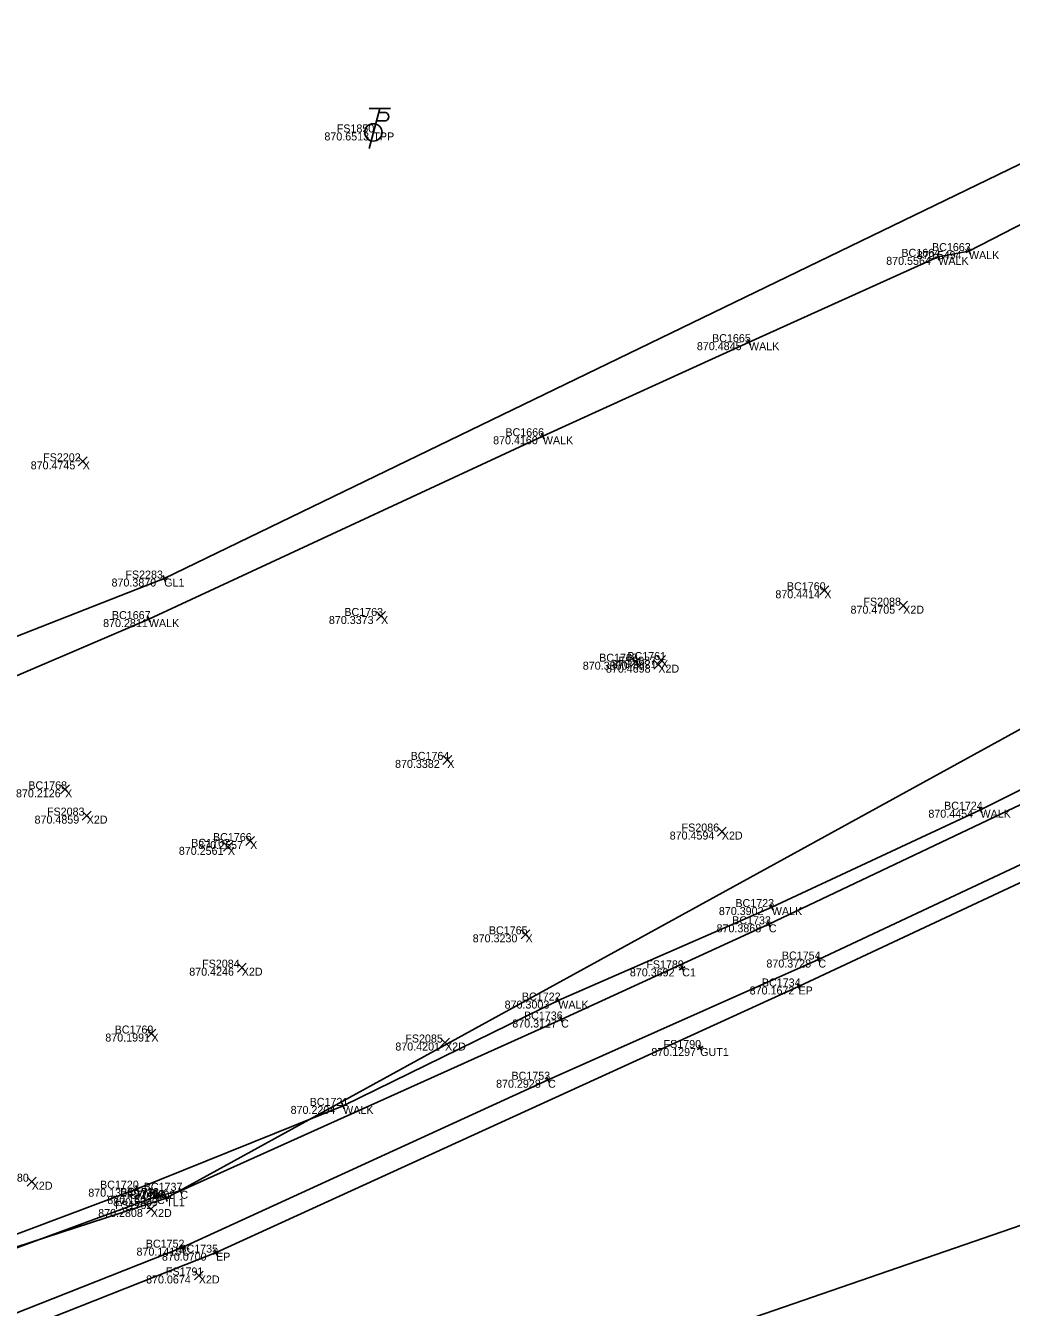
# Model space of a CAD drawing. Extents: x 1479425 to 1480294, y 379351 to 380102.
# Drawn here: x 1479669.9 to 1479677.28, y 379943.62 to 379953.22 of the extents above; entities that cross this region are included whole.
import ezdxf

# ---------------------------------------------------------------- set-up
doc = ezdxf.new("R2010")
doc.units = 0
for name, color, linetype in [('PV_X_Curb', 7, 'Continuous'), ('PV_X_Walk', 7, 'Continuous'), ('SV_X_Random_Point', 7, 'Continuous'), ('SV_X_Shot_Marker', 7, 'Continuous'), ('SV_X_Text_Comment', 7, 'Continuous'), ('SV_X_Text_Elevation', 7, 'Continuous'), ('SV_X_Text_Name', 7, 'Continuous'), ('UT_X_Gas', 7, 'Continuous'), ('UT_X_Misc_Cells', 7, 'Continuous'), ('UT_X_Sanitary_Line', 7, 'Continuous'), ('UT_X_Telecom', 7, 'Continuous')]:
    doc.layers.add(name, color=color, linetype=linetype)

msp = doc.modelspace()

# ---------------------------------------------------------------- linework, layer by layer
at = {"layer": 'PV_X_Curb'}
for points in [[(1479791.59, 380003.4635), (1479772.982, 379994.3805), (1479762.438, 379989.2296), (1479737.891, 379977.2252), (1479720.638, 379968.6113), (1479698.71, 379957.883), (1479682.4127, 379949.7895), (1479678.7563, 379947.9876), (1479678.5248, 379947.9422), (1479675.4654, 379946.4876), (1479673.9091, 379945.7738), (1479671.0561, 379944.4897), (1479670.8808, 379944.4504), (1479668.8369, 379943.6961), (1479667.0164, 379943.0245), (1479664.845, 379942.3912), (1479664.6467, 379942.3345), (1479664.117, 379942.1619), (1479661.876, 379941.9004), (1479659.999, 379941.9714), (1479653.935, 379943.2676), (1479649.182, 379945.5268), (1479644.261, 379948.8889)], [(1479791.848, 380002.9887), (1479773.254, 379993.8725), (1479762.766, 379988.7719), (1479738.122, 379976.6433), (1479720.845, 379968.2141), (1479698.694, 379957.2389), (1479682.744, 379949.3616), (1479678.8019, 379947.4796), (1479675.6873, 379946.0213), (1479671.3231, 379944.0259), (1479668.9901, 379943.1057), (1479665.6381, 379942.0412), (1479664.1435, 379941.5823), (1479662.026, 379941.3965), (1479659.994, 379941.5118), (1479654.023, 379942.7671), (1479648.758, 379945.1011), (1479643.81, 379948.5526)], [(1479664.2039, 379941.7379), (1479664.7376, 379941.8534), (1479664.9193, 379941.9176), (1479667.0854, 379942.5936), (1479669.0389, 379943.2625), (1479671.0702, 379944.0635), (1479673.8108, 379945.3222), (1479675.8363, 379946.2235), (1479678.7099, 379947.5729), (1479678.8669, 379947.6085), (1479682.6232, 379949.494)]]:
    msp.add_lwpolyline(points, dxfattribs=at)
at = {"layer": 'PV_X_Walk'}
for points in [[(1479680.531, 379953.5783), (1479680.5594, 379953.3846), (1479676.9646, 379951.5344), (1479676.7347, 379951.4915), (1479675.3165, 379950.8518), (1479673.7719, 379950.1464), (1479670.8196, 379948.7758), (1479669.4595, 379948.1937), (1479669.388, 379947.9546), (1479669.0403, 379947.6975), (1479668.7338, 379947.7557), (1479668.5535, 379947.8945), (1479667.7241, 379947.5602), (1479667.7995, 379947.6709), (1479667.4767, 379949.4768), (1479667.1248, 379951.2892), (1479667.1368, 379951.4103), (1479666.7498, 379953.3122), (1479666.5215, 379955.0904), (1479666.4393, 379955.1162), (1479666.0253, 379957.6131), (1479665.7712, 379958.9526), (1479665.7102, 379959.0342), (1479665.0761, 379962.8267)], [(1479668.8228, 379943.7878), (1479670.7322, 379944.5055), (1479672.2751, 379945.1262), (1479673.8874, 379945.9158), (1479675.4876, 379946.6168), (1479677.0508, 379947.3467), (1479678.4574, 379948.0505), (1479678.6848, 379948.0907), (1479682.4053, 379949.8566)]]:
    msp.add_lwpolyline(points, dxfattribs=at)
at = {"layer": 'SV_X_Random_Point'}
for p, q in [((1479670.2907, 379949.9251), (1479670.3573, 379949.9919)), ((1479670.2907, 379949.9919), (1479670.3573, 379949.9251)), ((1479675.8474, 379948.9584), (1479675.914, 379949.0252)), ((1479675.8474, 379949.0252), (1479675.914, 379948.9584)), ((1479676.4387, 379948.843), (1479676.5053, 379948.9098)), ((1479676.4387, 379948.9098), (1479676.5053, 379948.843)), ((1479672.5262, 379948.7656), (1479672.5928, 379948.8324)), ((1479672.5262, 379948.8324), (1479672.5928, 379948.7656)), ((1479674.4347, 379948.423), (1479674.5013, 379948.4898)), ((1479674.4347, 379948.4898), (1479674.5013, 379948.423)), ((1479674.6037, 379948.4009), (1479674.6703, 379948.4677)), ((1479674.6037, 379948.4677), (1479674.6703, 379948.4009)), ((1479674.6243, 379948.4351), (1479674.6909, 379948.5019)), ((1479674.6243, 379948.5019), (1479674.6909, 379948.4351)), ((1479673.0223, 379947.6867), (1479673.0889, 379947.7535)), ((1479673.0223, 379947.7535), (1479673.0889, 379947.6867)), ((1479670.1589, 379947.466), (1479670.2255, 379947.5328)), ((1479670.1589, 379947.5328), (1479670.2255, 379947.466)), ((1479670.3207, 379947.2691), (1479670.3873, 379947.3359)), ((1479670.3207, 379947.3359), (1479670.3873, 379947.2691)), ((1479675.0797, 379947.1495), (1479675.1463, 379947.2163)), ((1479675.0797, 379947.2163), (1479675.1463, 379947.1495)), ((1479671.3782, 379947.0349), (1479671.4448, 379947.1017)), ((1479671.3782, 379947.1017), (1479671.4448, 379947.0349)), ((1479671.5456, 379947.0781), (1479671.6122, 379947.1449)), ((1479671.5456, 379947.1449), (1479671.6122, 379947.0781)), ((1479673.6089, 379946.3791), (1479673.6755, 379946.4459)), ((1479673.6089, 379946.4459), (1479673.6755, 379946.3791)), ((1479671.4827, 379946.129), (1479671.5493, 379946.1958)), ((1479671.4827, 379946.1958), (1479671.5493, 379946.129)), ((1479670.8056, 379945.6351), (1479670.8722, 379945.7019)), ((1479670.8056, 379945.7019), (1479670.8722, 379945.6351)), ((1479673.0057, 379945.5679), (1479673.0723, 379945.6347)), ((1479673.0057, 379945.6347), (1479673.0723, 379945.5679)), ((1479669.9087, 379944.5244), (1479669.9753, 379944.5912)), ((1479669.9087, 379944.5912), (1479669.9753, 379944.5244)), ((1479670.8017, 379944.3197), (1479670.8683, 379944.3865)), ((1479670.8017, 379944.3865), (1479670.8683, 379944.3197)), ((1479671.1607, 379943.8214), (1479671.2273, 379943.8882)), ((1479671.1607, 379943.8882), (1479671.2273, 379943.8214))]:
    msp.add_line(p, q, dxfattribs=at)
at = {"layer": 'SV_X_Shot_Marker'}
for p, q in [((1479676.7593, 379951.4961), (1479676.7101, 379951.4869)), ((1479676.7393, 379951.4669), (1479676.7301, 379951.5161)), ((1479676.7347, 379951.4915), (1479676.7347, 379951.4915)), ((1479676.9868, 379951.5459), (1479676.9424, 379951.523)), ((1479676.976, 379951.5122), (1479676.9532, 379951.5566)), ((1479676.9646, 379951.5344), (1479676.9646, 379951.5344)), ((1479675.3393, 379950.8621), (1479675.2937, 379950.8415)), ((1479675.3268, 379950.829), (1479675.3062, 379950.8746)), ((1479675.3165, 379950.8518), (1479675.3165, 379950.8518)), ((1479673.7946, 379950.1568), (1479673.7492, 379950.136)), ((1479673.7823, 379950.1237), (1479673.7615, 379950.1692)), ((1479673.7719, 379950.1464), (1479673.7719, 379950.1464)), ((1479670.9117, 379949.0705), (1479670.9583, 379949.0887)), ((1479670.9259, 379949.1029), (1479670.9441, 379949.0563)), ((1479670.935, 379949.0796), (1479670.935, 379949.0796)), ((1479670.8301, 379948.7531), (1479670.8091, 379948.7985)), ((1479670.8423, 379948.7863), (1479670.7969, 379948.7653)), ((1479670.8196, 379948.7758), (1479670.8196, 379948.7758)), ((1479677.0281, 379947.3361), (1479677.0734, 379947.3573)), ((1479677.0402, 379947.3694), (1479677.0614, 379947.3241)), ((1479677.0508, 379947.3467), (1479677.0508, 379947.3467)), ((1479675.4647, 379946.6068), (1479675.5105, 379946.6269)), ((1479675.4776, 379946.6397), (1479675.4976, 379946.5939)), ((1479675.4876, 379946.6168), (1479675.4876, 379946.6168)), ((1479675.488, 379946.4984), (1479675.4428, 379946.4769)), ((1479675.4761, 379946.465), (1479675.4547, 379946.5102)), ((1479675.4654, 379946.4876), (1479675.4654, 379946.4876)), ((1479675.8135, 379946.2134), (1479675.8591, 379946.2337)), ((1479675.8261, 379946.2464), (1479675.8465, 379946.2007)), ((1479675.8363, 379946.2235), (1479675.8363, 379946.2235)), ((1479674.8383, 379946.1685), (1479674.7937, 379946.1458)), ((1479674.8273, 379946.1348), (1479674.8047, 379946.1794)), ((1479674.816, 379946.1571), (1479674.816, 379946.1571)), ((1479675.7099, 379946.0319), (1479675.6647, 379946.0107)), ((1479675.6979, 379945.9987), (1479675.6767, 379946.044)), ((1479675.6873, 379946.0213), (1479675.6873, 379946.0213)), ((1479673.8649, 379945.9048), (1479673.9098, 379945.9268)), ((1479673.8764, 379945.9383), (1479673.8984, 379945.8934)), ((1479673.8874, 379945.9158), (1479673.8874, 379945.9158)), ((1479673.9318, 379945.7842), (1479673.8864, 379945.7634)), ((1479673.9195, 379945.7511), (1479673.8987, 379945.7965)), ((1479673.9091, 379945.7738), (1479673.9091, 379945.7738)), ((1479674.9732, 379945.5715), (1479674.9287, 379945.5487)), ((1479674.9624, 379945.5379), (1479674.9396, 379945.5824)), ((1479674.951, 379945.5601), (1479674.951, 379945.5601)), ((1479673.8004, 379945.3449), (1479673.8212, 379945.2995)), ((1479673.7881, 379945.3118), (1479673.8335, 379945.3327)), ((1479673.8108, 379945.3222), (1479673.8108, 379945.3222)), ((1479672.2658, 379945.1494), (1479672.2844, 379945.103)), ((1479672.2519, 379945.1169), (1479672.2983, 379945.1356)), ((1479672.2751, 379945.1262), (1479672.2751, 379945.1262)), ((1479670.7088, 379944.4967), (1479670.7556, 379944.5143)), ((1479670.7234, 379944.5289), (1479670.741, 379944.4821)), ((1479670.7322, 379944.5055), (1479670.7322, 379944.5055)), ((1479670.8863, 379944.426), (1479670.8753, 379944.4748)), ((1479671.0789, 379944.5), (1479671.0333, 379944.4795)), ((1479671.0664, 379944.4669), (1479671.0458, 379944.5125)), ((1479671.0561, 379944.4897), (1479671.0561, 379944.4897)), ((1479670.9052, 379944.4559), (1479670.8564, 379944.445)), ((1479670.8808, 379944.4504), (1479670.8808, 379944.4504)), ((1479670.9262, 379944.4265), (1479670.9738, 379944.442)), ((1479670.9422, 379944.458), (1479670.9577, 379944.4105)), ((1479670.95, 379944.4342), (1479670.95, 379944.4342)), ((1479671.061, 379944.0868), (1479671.0794, 379944.0403)), ((1479671.0469, 379944.0543), (1479671.0935, 379944.0727)), ((1479671.0702, 379944.0635), (1479671.0702, 379944.0635)), ((1479671.3458, 379944.0363), (1479671.3004, 379944.0155)), ((1479671.3335, 379944.0032), (1479671.3127, 379944.0487)), ((1479671.3231, 379944.0259), (1479671.3231, 379944.0259))]:
    msp.add_line(p, q, dxfattribs=at)
at = {"layer": 'UT_X_Gas'}
msp.add_lwpolyline([(1479646.785, 379955.4381), (1479652.981, 379949.4327), (1479657.465, 379945.9636), (1479660.591, 379945.0242), (1479670.935, 379949.0796), (1479679.157, 379953.0651), (1479685.442, 379955.7424), (1479689.462, 379958.1268), (1479696.956, 379963.0127), (1479705.088, 379967.4878), (1479713.465, 379971.2262), (1479723.024, 379975.6759), (1479732.065, 379980.116), (1479742.535, 379985.0181), (1479753.798, 379990.643), (1479767.065, 379997.4563), (1479775.982, 380001.7332), (1479789.966, 380007.7888)], dxfattribs=at)
at = {"layer": 'UT_X_Misc_Cells'}
for p, q in [((1479672.5502, 379952.6041), (1479672.4698, 379952.3041)), ((1479672.6302, 379952.6041), (1479672.4702, 379952.6041)), ((1479672.5422, 379952.5741), (1479672.5847, 379952.5741)), ((1479672.5251, 379952.5104), (1479672.5847, 379952.5104))]:
    msp.add_line(p, q, dxfattribs=at)
msp.add_circle((1479672.502, 379952.4241), 0.065, dxfattribs=at)
msp.add_arc((1479672.5853, 379952.5422), 0.0319, 268.8767, 91.1233, dxfattribs=at)
at = {"layer": 'UT_X_Sanitary_Line'}
msp.add_lwpolyline([(1479514.622, 379866.8703), (1479542.109, 379880.1949), (1479565.169, 379891.7253), (1479588.442, 379902.5771), (1479600.276, 379909.0452), (1479620.421, 379921.0629), (1479621.963, 379921.4851), (1479624.647, 379923.4166), (1479645.234, 379932.5118), (1479652.585, 379935.6159), (1479664.157, 379939.675), (1479679.103, 379944.837), (1479710.112, 379956.4476), (1479736.037, 379968.2328), (1479798.147, 379991.1675), (1479820.4, 379999.933), (1479823.042, 380000.22)], dxfattribs=at)
at = {"layer": 'UT_X_Telecom'}
msp.add_lwpolyline([(1479654.736, 379936.5803), (1479659.767, 379940.788), (1479670.95, 379944.4342), (1479693.183, 379956.6524)], dxfattribs=at)

# ---------------------------------------------------------------- texts
at = {"layer": 'SV_X_Text_Comment'}
for s, p in [('TPP', (1479672.502, 379952.3641)), ('WALK', (1479676.7347, 379951.4315)), ('WALK', (1479676.9646, 379951.4744)), ('WALK', (1479675.3165, 379950.7918)), ('WALK', (1479673.7719, 379950.0864)), ('X', (1479670.324, 379949.8985)), ('GL1', (1479670.935, 379949.0196)), ('X', (1479675.8807, 379948.9318)), ('X', (1479672.5595, 379948.739)), ('X2D', (1479676.472, 379948.8164)), ('WALK', (1479670.8196, 379948.7158)), ('X', (1479674.468, 379948.3964)), ('X2D', (1479674.637, 379948.3743)), ('X', (1479674.6576, 379948.4085)), ('X', (1479673.0556, 379947.6601)), ('X', (1479670.1922, 379947.4394)), ('X2D', (1479670.354, 379947.2425)), ('WALK', (1479677.0508, 379947.2867)), ('X2D', (1479675.113, 379947.1229)), ('X', (1479671.4115, 379947.0083)), ('X', (1479671.5789, 379947.0515)), ('WALK', (1479675.4876, 379946.5568)), ('C', (1479675.4654, 379946.4276)), ('X', (1479673.6422, 379946.3525)), ('C', (1479675.8363, 379946.1635)), ('X2D', (1479671.516, 379946.1024)), ('C1', (1479674.816, 379946.0971)), ('EP', (1479675.6873, 379945.9613)), ('WALK', (1479673.8874, 379945.8558)), ('C', (1479673.9091, 379945.7138)), ('X', (1479670.8389, 379945.6085)), ('X2D', (1479673.039, 379945.5413)), ('GUT1', (1479674.951, 379945.5001)), ('C', (1479673.8108, 379945.2622)), ('WALK', (1479672.2751, 379945.0662)), ('X2D', (1479669.942, 379944.4978)), ('WALK', (1479670.7322, 379944.4455)), ('C', (1479671.0561, 379944.4297)), ('C', (1479670.8808, 379944.3904)), ('TL1', (1479670.95, 379944.3742)), ('X2D', (1479670.835, 379944.2931)), ('C', (1479671.0702, 379944.0035)), ('EP', (1479671.3231, 379943.9659)), ('X2D', (1479671.194, 379943.7948))]:
    msp.add_text(s, height=0.06, dxfattribs=at).set_placement(p)
at = {"layer": 'SV_X_Text_Elevation'}
for s, p in [('870.6513', (1479672.135, 379952.3641)), ('870.5564', (1479676.3445, 379951.4315)), ('870.5494', (1479676.5739, 379951.4744)), ('870.4845', (1479674.9258, 379950.7918)), ('870.4160', (1479673.3992, 379950.0864)), ('870.4745', (1479669.9343, 379949.8985)), ('870.3870', (1479670.5401, 379949.0196)), ('870.4414', (1479675.5141, 379948.9318)), ('870.3373', (1479672.1688, 379948.739)), ('870.4705', (1479676.0771, 379948.8164)), ('870.2811', (1479670.477, 379948.7158)), ('870.3860', (1479674.0712, 379948.3964)), ('870.4698', (1479674.2444, 379948.3743)), ('870.3921', (1479674.2895, 379948.4085)), ('870.3382', (1479672.6644, 379947.6601)), ('870.2126', (1479669.8242, 379947.4394)), ('870.4859', (1479669.9633, 379947.2425)), ('870.4454', (1479676.6606, 379947.2867)), ('870.4594', (1479674.7223, 379947.1229)), ('870.2561', (1479671.0443, 379947.0083)), ('870.2557', (1479671.1901, 379947.0515)), ('870.3902', (1479675.0908, 379946.5568)), ('870.3868', (1479675.0733, 379946.4276)), ('870.3230', (1479673.2463, 379946.3525)), ('870.3728', (1479675.447, 379946.1635)), ('870.4246', (1479671.1225, 379946.1024)), ('870.3692', (1479674.4239, 379946.0971)), ('870.1672', (1479675.3217, 379945.9613)), ('870.3003', (1479673.4854, 379945.8558)), ('870.3127', (1479673.543, 379945.7138)), ('870.1991', (1479670.4935, 379945.6085)), ('870.4201', (1479672.6666, 379945.5413)), ('870.1297', (1479674.5849, 379945.5001)), ('870.2928', (1479673.4215, 379945.2622)), ('870.2204', (1479671.882, 379945.0662)), ('870.1323', (1479670.3661, 379944.4455)), ('870.1608', (1479670.6829, 379944.4297)), ('870.1602', (1479670.5086, 379944.3904)), ('870.3309', (1479670.5522, 379944.3742)), ('870.2808', (1479670.4401, 379944.2931)), ('870.1415', (1479670.7273, 379944.0035)), ('870.0700', (1479670.9178, 379943.9659)), ('870.0674', (1479670.7991, 379943.7948))]:
    msp.add_text(s, height=0.06, dxfattribs=at).set_placement(p)
at = {"layer": 'SV_X_Text_Name'}
for s, p in [('FS1850', (1479672.2276, 379952.4241)), ('BC1663', (1479676.6878, 379951.5344)), ('BC1664', (1479676.4584, 379951.4915)), ('BC1665', (1479675.0397, 379950.8518)), ('BC1666', (1479673.4913, 379950.1464)), ('FS2202', (1479670.0278, 379949.9585)), ('FS2283', (1479670.644, 379949.0796)), ('BC1760', (1479675.6006, 379948.9918)), ('FS2088', (1479676.1739, 379948.8764)), ('BC1667', (1479670.5428, 379948.7758)), ('BC1763', (1479672.2846, 379948.799)), ('BC1762', (1479674.1936, 379948.4564)), ('BC1761', (1479674.4052, 379948.4685)), ('FS2087', (1479674.3394, 379948.4343)), ('BC1764', (1479672.7812, 379947.7201)), ('BC1768', (1479669.9168, 379947.4994)), ('FS2083', (1479670.0564, 379947.3025)), ('BC1724', (1479676.7782, 379947.3467)), ('BC1766', (1479671.3002, 379947.1115)), ('FS2086', (1479674.8116, 379947.1829)), ('BC1767', (1479671.1366, 379947.0683)), ('BC1723', (1479675.2146, 379946.6168)), ('BC1733', (1479675.1905, 379946.4876)), ('BC1765', (1479673.3673, 379946.4125)), ('FS2084', (1479671.2189, 379946.1624)), ('FS1789', (1479674.5472, 379946.1571)), ('BC1754', (1479675.5628, 379946.2235)), ('BC1734', (1479675.4129, 379946.0213)), ('BC1722', (1479673.6148, 379945.9158)), ('BC1736', (1479673.6304, 379945.7738)), ('BC1769', (1479670.5635, 379945.6685)), ('FS2085', (1479672.7414, 379945.6013)), ('FS1790', (1479674.6766, 379945.5601)), ('BC1753', (1479673.5368, 379945.3222)), ('BC1721', (1479672.0246, 379945.1262)), ('FS2080', (1479669.6392, 379944.5578)), ('BC1720', (1479670.454, 379944.5055)), ('BC1738', (1479670.6054, 379944.4504)), ('FS2486', (1479670.6538, 379944.4342)), ('BC1737', (1479670.7812, 379944.4897)), ('FS1792', (1479670.5662, 379944.3531)), ('BC1752', (1479670.7967, 379944.0635)), ('BC1735', (1479671.0482, 379944.0259)), ('FS1791', (1479670.9473, 379943.8548))]:
    msp.add_text(s, height=0.06, dxfattribs=at).set_placement(p)

doc.saveas('drawing.dxf')
